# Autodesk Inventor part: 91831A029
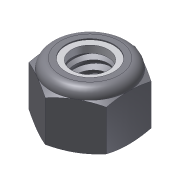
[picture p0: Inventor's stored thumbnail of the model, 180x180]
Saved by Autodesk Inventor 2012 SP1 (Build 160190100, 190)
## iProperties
Created: 2012-03
Part Number: 91831A029
Material: Stainless Steel
Document SubType Name: Modeling
Designer: jdh
Mass: 4.84058 g
Surface Area: 9.10252 cm^2
Volume: 0.599081 cm^3
Density: 8.08 g/cm^3
Translation Standard: STEP AP203
FileName: 91831A029.step
PreProcessor: SolidWorks 2007
PostProcessor: Build: 190, Release: 2012 SP1 - Date: Mon 08/08/2011
Sent Units: inch
Uncertainty: 1e-05
Author: jdh
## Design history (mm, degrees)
node "91831A0291"
node "NONE"
node "NONE_1"
node "Base1"
node "Base2"
